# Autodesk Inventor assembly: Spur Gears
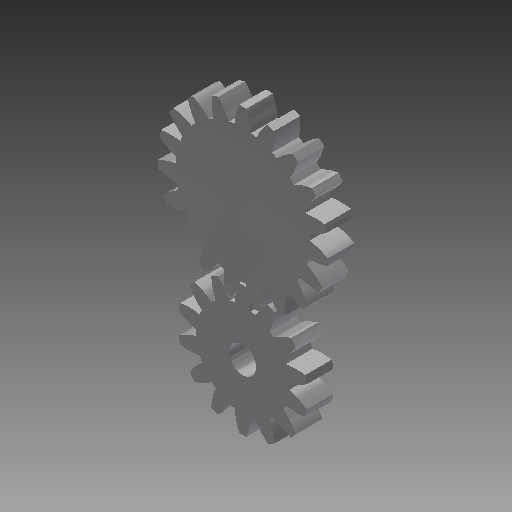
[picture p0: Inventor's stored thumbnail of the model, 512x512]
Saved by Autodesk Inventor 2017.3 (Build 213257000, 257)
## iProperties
Created: 2020-03
Part Number: Spur Gears
Document SubType Name: Assembly
Designer: Tim_G
Categories: <?xml version="1.0" encoding="UTF-16"?> <MemberInstance><Categories><FamilyTemplate/><ParamToTemplateMap><ParamToTemplate><ParamToTemplate CategoryParameter="//
ClientObjectVersion: 1
Author: Tim_G
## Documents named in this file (3)
- C:\Users\Tim_G\OneDrive - McMaster University\Documents\Documents\Books\McMaster First Year Courses\Winter Engineering 1C03\Project\Project Files (Prosthetic Frame Assembly)\Hand Assembly\Design Accelerator\Spur Gears6.iam
- C:\Users\Tim_G\OneDrive - McMaster University\Documents\Documents\Books\McMaster First Year Courses\Winter Engineering 1C03\Project\Project Files (Prosthetic Frame Assembly)\Hand Assembly\Design Accelerator\Spur Gear16.ipt
- C:\Users\Tim_G\OneDrive - McMaster University\Documents\Documents\Books\McMaster First Year Courses\Winter Engineering 1C03\Project\Project Files (Prosthetic Frame Assembly)\Hand Assembly\Design Accelerator\Spur Gear26.ipt
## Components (2 placed, 2 different names)
1. Spur Gear1:1 — Rotation:1
2. Spur Gear2:1 — Rotation:1
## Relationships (1: RelateRotation 1)
- Rotation:1 [RelateRotation]: Spur Gear1:1 ↔ Spur Gear2:1
